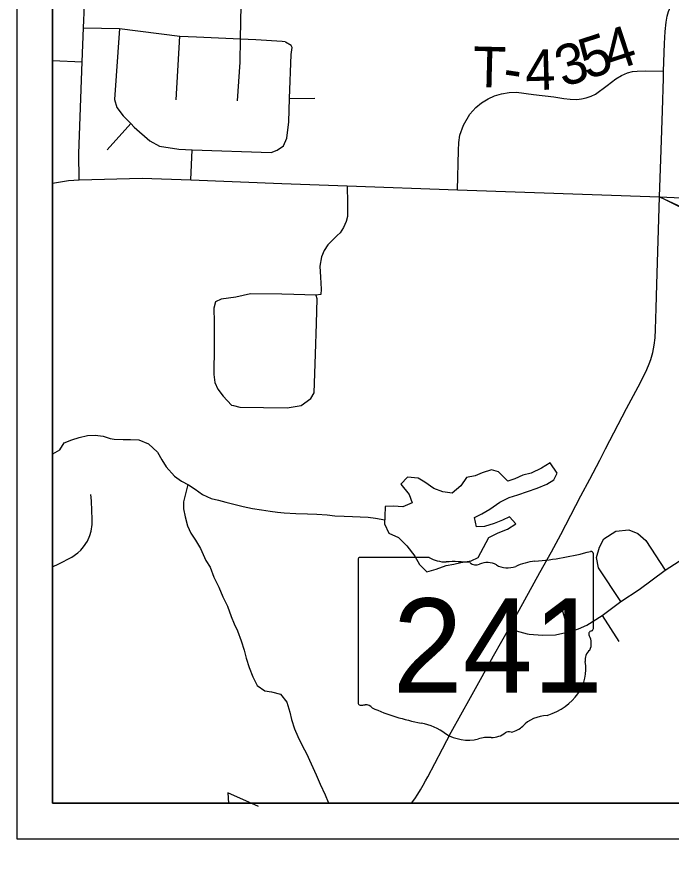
# Model space of a CAD drawing. Extents: x 25.6 to 80.6, y 0.2 to 24.5.
# Drawn here: x 37.513 to 39.345, y 14.165 to 16.534 of the extents above; entities that cross this region are included whole.
import ezdxf

# ---------------------------------------------------------------- set-up
doc = ezdxf.new("R2010")
doc.units = 0
for name, color, linetype in [('GM_X_Minor_Lake', 7, 'Continuous'), ('GM_X_Minor_River', 7, 'Continuous'), ('GM_X_State_Route', 7, 'Continuous'), ('GM_X_State_Shield', 7, 'Continuous'), ('GM_X_Township_Road', 7, 'Continuous'), ('GM_X_Township_Road_Text', 7, 'Continuous'), ('SH_Data', 7, 'Continuous'), ('SH_Text', 7, 'Continuous')]:
    doc.layers.add(name, color=color, linetype=linetype)

msp = doc.modelspace()

# ---------------------------------------------------------------- linework, layer by layer
at = {"layer": 'GM_X_Minor_Lake'}
msp.add_line((38.1036, 14.359), (38.1053, 14.3303), dxfattribs=at)
for points in [[(38.8344, 15.0752), (38.8607, 15.0877), (38.8871, 15.0987), (38.9105, 15.1135), (38.8927, 15.133), (38.8731, 15.1236), (38.8498, 15.1142), (38.8226, 15.1062), (38.7998, 15.1051), (38.7949, 15.1309), (38.8152, 15.1411), (38.8378, 15.1543), (38.8656, 15.1744), (38.8913, 15.187), (38.9162, 15.1949), (38.9434, 15.2036), (38.9698, 15.2131), (38.9977, 15.2242), (39.0173, 15.2366), (39.0261, 15.2557), (39.0068, 15.2843), (38.9827, 15.2695), (38.9533, 15.2555), (38.9299, 15.2498), (38.908, 15.2396), (38.8884, 15.2333), (38.8622, 15.2587), (38.8424, 15.2645), (38.816, 15.2558), (38.7963, 15.2479), (38.7721, 15.243), (38.7565, 15.22), (38.7325, 15.1992), (38.7059, 15.2026), (38.6807, 15.2121), (38.6555, 15.23), (38.6364, 15.2411), (38.6067, 15.2445), (38.588, 15.2245), (38.6112, 15.1959), (38.6198, 15.1717), (38.5942, 15.1607), (38.5676, 15.1626), (38.5441, 15.1616), (38.543, 15.1342), (38.5425, 15.1129), (38.555, 15.0872), (38.5817, 15.0747), (38.6055, 15.0515), (38.6279, 15.0229), (38.6404, 14.9995), (38.6612, 14.9785), (38.6876, 14.9858), (38.7148, 14.996), (38.7367, 15.0001), (38.7564, 15.005), (38.7852, 15.0099), (38.8048, 15.0186)], [(38.8048, 15.0186), (38.8344, 15.0752)], [(38.1891, 14.3207), (38.1036, 14.359)]]:
    msp.add_lwpolyline(points, dxfattribs=at)
at = {"layer": 'GM_X_Minor_River'}
for points in [[(37.6128, 15.3089), (37.6135, 15.3095), (37.6332, 15.3209), (37.6452, 15.3399), (37.6664, 15.3484), (37.6876, 15.3553), (37.7103, 15.3607), (37.7316, 15.3615), (37.7543, 15.3586), (37.7741, 15.3526), (37.7855, 15.3503)], [(37.7855, 15.3503), (37.8102, 15.3496), (37.8314, 15.3499), (37.8542, 15.3487), (37.8816, 15.3377), (37.9062, 15.3137), (37.9187, 15.2926), (37.9311, 15.273), (37.9542, 15.2467), (37.9741, 15.2333), (37.9932, 15.223), (38.0124, 15.2103), (38.033, 15.1954), (38.0567, 15.1843), (38.0773, 15.1793), (38.0978, 15.1743), (38.1245, 15.1678), (38.1465, 15.1621), (38.1724, 15.1563), (38.1983, 15.1521), (38.2218, 15.1487), (38.2424, 15.1459), (38.2614, 15.1439), (38.294, 15.1421), (38.3266, 15.141), (38.3525, 15.1399), (38.3821, 15.138), (38.4033, 15.136), (38.4292, 15.1349), (38.4527, 15.1337), (38.4747, 15.1332), (38.4967, 15.132), (38.5172, 15.1293), (38.5431, 15.1243)], [(37.9917, 15.2238), (37.9795, 15.1749), (37.979, 15.1551), (37.9838, 15.1332), (37.991, 15.1074), (38.0004, 15.087), (38.0128, 15.0675), (38.0275, 15.0441), (38.0424, 15.0109), (38.054, 14.9913), (38.0643, 14.9641), (38.0783, 14.9354), (38.09, 14.909), (38.1025, 14.8825), (38.1128, 14.8538), (38.1214, 14.8327), (38.1308, 14.813), (38.141, 14.7851), (38.149, 14.7593), (38.1554, 14.7366), (38.1633, 14.7109), (38.1735, 14.6845), (38.186, 14.6596), (38.2074, 14.6454), (38.2264, 14.6426), (38.2516, 14.6354), (38.2693, 14.6129), (38.2773, 14.5856), (38.2821, 14.5644), (38.2901, 14.5387), (38.2995, 14.5168), (38.3127, 14.4896), (38.3236, 14.4692), (38.3369, 14.4405), (38.351, 14.4096), (38.362, 14.3831), (38.376, 14.3537), (38.3847, 14.3333), (38.3858, 14.3303)]]:
    msp.add_lwpolyline(points, dxfattribs=at)
at = {"layer": 'GM_X_State_Route'}
for points in [[(39.3238, 16.3625), (39.3244, 16.3819), (39.3264, 16.46), (39.3283, 16.4933), (39.3314, 16.5193), (39.3346, 16.536), (39.3383, 16.5496), (39.3443, 16.5648), (39.3498, 16.5756), (39.3866, 16.6383), (39.464, 16.7577), (39.475, 16.7749)], [(39.3128, 16.0303), (39.3174, 16.1619), (39.3211, 16.2713), (39.3238, 16.3625)], [(39.1453, 15.2918), (39.1618, 15.3235), (39.2208, 15.4361), (39.2596, 15.5098), (39.2773, 15.5456), (39.2842, 15.5614), (39.2886, 15.5738), (39.2942, 15.5939), (39.2983, 15.6137), (39.3008, 15.6351), (39.302, 15.658), (39.3033, 15.7182), (39.3051, 15.7842), (39.3128, 16.0303)], [(39.3128, 16.0303), (39.6229, 16.0159), (40.0335, 16.0001)], [(38.6184, 14.3303), (38.6275, 14.3425), (38.636, 14.3555), (38.6434, 14.3677), (38.6505, 14.3803), (38.6573, 14.3924), (38.6635, 14.4043), (38.6832, 14.4412), (38.7053, 14.4828), (38.7296, 14.5289), (38.7561, 14.5777), (38.7835, 14.6268), (38.8157, 14.6848), (38.8483, 14.7433), (38.8715, 14.7845), (38.8907, 14.8188), (38.9193, 14.871), (38.9778, 14.9764), (39.0103, 15.0349), (39.0363, 15.0833), (39.0926, 15.1913), (39.1177, 15.2389), (39.1453, 15.2918)]]:
    msp.add_lwpolyline(points, dxfattribs=at)
at = {"layer": 'GM_X_State_Shield'}
for p, q in [((39.1276, 14.8198), (39.1276, 15.0292)), ((38.4685, 15.0124), (38.4685, 14.6122)), ((38.668, 15.0193), (38.475, 15.0193)), ((39.1276, 14.8199), (39.1276, 14.8198))]:
    msp.add_line(p, q, dxfattribs=at)
for centre, major_axis, start_param, end_param in [((38.8928, 15.5649), (0.699, 0), 4.814394, 5.042369), ((39.1203, 15.0301), (0.00734, 0), 6.141152, 7.989035), ((38.476, 15.0132), (0.00764, 0), 1.712693, 3.28349), ((38.714, 15.0657), (0.0741, 0), 4.042523, 4.731795), ((38.7385, 14.7946), (0.2659, 0), 1.404758, 1.657858), ((38.7989, 15.0153), (0.0214, 0), 3.836095, 5.185415), ((38.8303, 14.9691), (0.0444, 0), 0.950623, 2.079405), ((38.8876, 15.0325), (0.0534, 0), 4.081561, 5.145723), ((38.982, 14.897), (0.1406, 0), 1.699011, 2.107814), ((39.126, 14.8045), (0.0114, 0), 1.883978, 3.671073), ((39.1198, 14.819), (0.00785, 0), 5.05454, 6.418171), ((39.0537, 14.778), (0.0682, 0), 5.934695, 6.695948), ((39.1539, 14.7322), (0.0496, 0), 2.387724, 3.262537), ((38.932, 14.7056), (0.1748, 0), 5.101752, 6.440018), ((38.4761, 14.6113), (0.0077, 0), 3.00124, 4.508301), ((38.4773, 14.6522), (0.0588, 0), 4.665946, 4.897461), ((38.4893, 14.5891), (0.0212, 0), 0.519207, 1.627899), ((38.7569, 14.9487), (0.5048, 0), 4.195997, 4.488961), ((39.0057, 14.4998), (0.0958, 0), 1.647645, 2.488434), ((38.6065, 14.4323), (0.1579, 0), 0.823519, 1.323587), ((38.7773, 14.5871), (0.1002, 0), 4.026481, 4.996735), ((38.8425, 14.5571), (0.0534, 0), 4.691044, 5.507374), ((38.8908, 14.5183), (0.015, 0), 1.147584, 2.315152), ((38.8844, 14.5734), (0.0565, 0), 4.937069, 5.64225), ((38.8352, 14.4487), (0.0824, 0), 1.495662, 1.94098)]:
    msp.add_ellipse(centre, major_axis=major_axis, ratio=0.8, start_param=start_param, end_param=end_param, dxfattribs=at)
at = {"layer": 'GM_X_Township_Road'}
for p, q in [((37.959, 16.302), (37.9692, 16.4802)), ((37.6128, 16.4119), (37.696, 16.4082)), ((38.2768, 16.3055), (38.3478, 16.3063)), ((37.7659, 16.162), (37.8315, 16.2358)), ((38.0001, 16.0776), (38.0034, 16.162)), ((39.0588, 14.8105), (39.0386, 14.8802)), ((39.1527, 14.8559), (39.1989, 14.7838))]:
    msp.add_line(p, q, dxfattribs=at)
for points in [[(37.6868, 16.0774), (37.6864, 16.1517), (37.696, 16.4082), (37.6996, 16.5032), (37.7081, 16.6949), (37.7167, 16.9113), (37.7242, 17.1227), (37.743, 17.5857), (37.7473, 17.7303)], [(38.1309, 16.2991), (38.1383, 16.4072), (38.1394, 16.4731), (38.1409, 16.5676), (38.1463, 16.649), (38.1469, 16.665), (38.1475, 16.6787), (38.1515, 16.7351), (38.1621, 16.8395), (38.169, 16.8946)], [(37.6996, 16.5032), (37.7999, 16.5019), (37.9692, 16.4802), (38.0155, 16.4787), (38.1394, 16.4731), (38.1822, 16.4711), (38.2557, 16.4662), (38.2641, 16.465), (38.2649, 16.4635)], [(37.7999, 16.5019), (37.7858, 16.3025), (37.7926, 16.2799), (37.8109, 16.2571), (37.8315, 16.2358), (37.8415, 16.2255), (37.8853, 16.1869), (37.9123, 16.1719), (37.9663, 16.1632), (38.0034, 16.162), (38.2254, 16.1545), (38.2418, 16.1604), (38.2595, 16.1732), (38.2693, 16.1948), (38.2745, 16.2406), (38.2768, 16.3055), (38.2813, 16.4291), (38.2836, 16.4482), (38.2811, 16.4542), (38.2649, 16.4635)], [(38.7471, 16.0498), (38.75, 16.1599), (38.7508, 16.182), (38.754, 16.2024), (38.7638, 16.2311), (38.782, 16.2615), (38.7986, 16.2802), (38.8142, 16.2931), (38.8325, 16.3047), (38.8505, 16.3127), (38.8702, 16.3191), (38.8915, 16.3226), (38.9122, 16.3236), (38.96, 16.3171), (39.017, 16.3099), (39.0452, 16.306), (39.0624, 16.3038), (39.0812, 16.3032), (39.0941, 16.3043), (39.1071, 16.307), (39.1219, 16.3119), (39.1337, 16.3181), (39.1667, 16.3418), (39.1906, 16.3603), (39.2061, 16.3703), (39.2232, 16.3772), (39.2369, 16.3809), (39.2504, 16.3826), (39.2738, 16.3829), (39.3244, 16.3819)], [(37.6128, 16.0684), (37.6572, 16.0754), (37.6868, 16.0774), (37.8633, 16.082), (38.0001, 16.0776), (38.2552, 16.0676)], [(38.2552, 16.0676), (38.4378, 16.0605), (38.7471, 16.0498), (39.3128, 16.0303)], [(38.4378, 16.0605), (38.4392, 16.0121), (38.4385, 15.9745), (38.435, 15.9606), (38.428, 15.9438), (38.4183, 15.9294), (38.4103, 15.9219)], [(38.4103, 15.9219), (38.4024, 15.9144), (38.3836, 15.8951), (38.3735, 15.8798), (38.3661, 15.8619), (38.361, 15.8357), (38.3628, 15.8045), (38.3654, 15.7709), (38.3639, 15.7557), (38.3506, 15.7543), (38.2882, 15.7564)], [(38.2882, 15.7564), (38.2552, 15.7575), (38.1671, 15.7579), (38.1263, 15.7489), (38.0852, 15.7431), (38.0693, 15.7351), (38.0642, 15.7178), (38.065, 15.6781), (38.065, 15.5907), (38.0645, 15.5523)], [(38.3491, 15.5884), (38.3516, 15.6745), (38.3542, 15.7442), (38.3509, 15.7532)], [(38.1194, 15.445), (38.1372, 15.4405), (38.27, 15.4384), (38.309, 15.4448), (38.3358, 15.4643), (38.3459, 15.4802), (38.3491, 15.5884)], [(38.0645, 15.5523), (38.0642, 15.5322), (38.0671, 15.5098), (38.0758, 15.4903), (38.0902, 15.4708), (38.1141, 15.4463), (38.1194, 15.445)], [(37.6128, 14.9927), (37.6303, 15.0011), (37.6665, 15.0199), (37.683, 15.0315), (37.6918, 15.0395), (37.6996, 15.0486), (37.7101, 15.0644), (37.717, 15.0806), (37.7205, 15.0927), (37.7234, 15.1114), (37.7236, 15.1277), (37.7231, 15.1494), (37.7217, 15.1775), (37.7196, 15.195)], [(39.205, 14.8957), (39.1422, 14.9895), (39.1361, 15.0186), (39.1445, 15.0477), (39.1568, 15.0715), (39.1905, 15.093), (39.2265, 15.096), (39.2518, 15.0861), (39.2748, 15.0661), (39.3288, 14.9829)], [(38.948, 14.804), (38.9851, 14.8007), (39.0214, 14.8023), (39.0588, 14.8105), (39.0857, 14.8187), (39.109, 14.8287), (39.1527, 14.8559), (39.205, 14.8957), (39.2563, 14.9294), (39.3288, 14.9829), (39.3939, 15.0258), (39.3954, 15.0269)], [(38.8907, 14.8188), (38.9422, 14.8045), (38.948, 14.804)]]:
    msp.add_lwpolyline(points, dxfattribs=at)
at = {"layer": 'SH_Data'}
for p, q in [((37.5128, 21.2303), (37.5128, 14.2303)), ((37.6128, 21.1303), (37.6128, 14.3303)), ((37.6128, 21.1303), (37.6128, 14.3303)), ((37.6128, 14.3303), (44.4128, 14.3303)), ((37.6128, 14.3303), (37.6128, 14.3303)), ((37.6128, 14.3303), (44.4128, 14.3303)), ((37.5128, 14.2303), (47.9128, 14.2303))]:
    msp.add_line(p, q, dxfattribs=at)
at = {"layer": 'SH_Text'}
for points in [[(37.6128, 21.1303), (44.4128, 21.1303), (44.4128, 14.3303), (37.6128, 14.3303)], [(37.6128, 21.1303), (44.4128, 21.1303), (44.4128, 14.3303), (37.6128, 14.3303)], [(37.6128, 14.3303), (41.0128, 14.3303), (41.0128, 17.7303), (37.6128, 17.7303)], [(37.6128, 14.3303), (41.0128, 14.3303), (41.0128, 17.7303), (37.6128, 17.7303)], [(44.9027, 13.4418), (44.9027, 13.2418), (39.3128, 16.0303)]]:
    msp.add_lwpolyline(points, close=True, dxfattribs=at)

# ---------------------------------------------------------------- texts
at = {"layer": 'GM_X_State_Shield'}
msp.add_text('241', height=0.26367, dxfattribs=at).set_placement((38.5656, 14.6404))
at = {"layer": 'GM_X_Township_Road_Text'}
for s, rotation, p in [('4', 18.1487, (39.1763, 16.3798)), ('5', 17.9988, (39.1094, 16.3581)), ('T', 358.5727, (38.7887, 16.3381)), ('4', 1.6719, (38.938, 16.3282)), ('3', 18.1668, (39.043, 16.3363)), ('-', 351.5862, (38.8701, 16.3363))]:
    msp.add_text(s, height=0.1136, rotation=rotation, dxfattribs=at).set_placement(p)

doc.saveas('drawing.dxf')
